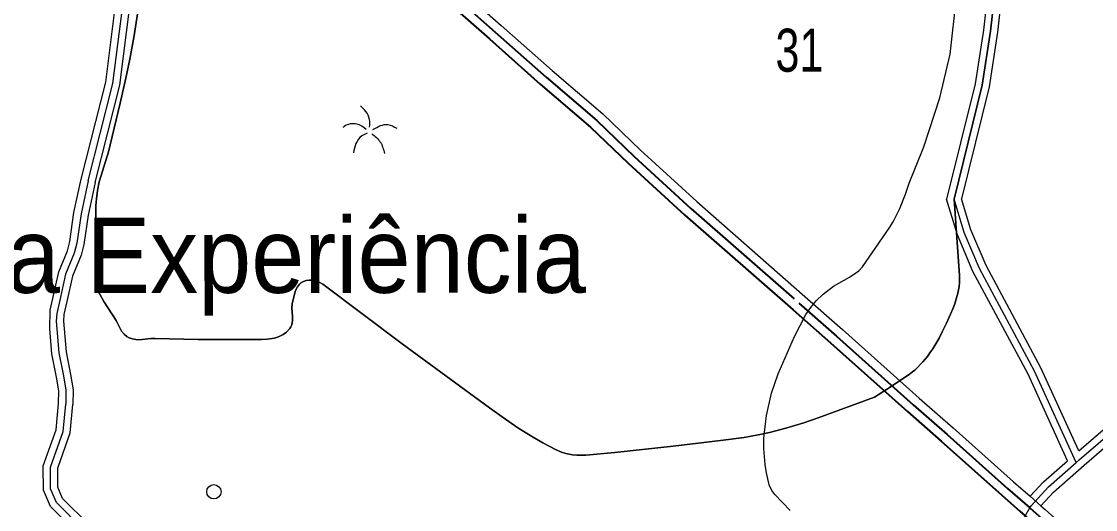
# Model space of a CAD drawing. Extents: x -64005 to -55000, y -89025 to -80000.
# Drawn here: x -59654 to -58155, y -88019 to -87338 of the extents above; entities that cross this region are included whole.
import ezdxf
from ezdxf.enums import TextEntityAlignment as Align

# ---------------------------------------------------------------- set-up
doc = ezdxf.new("R2010")
doc.units = 0
doc.header["$LTSCALE"] = 32
doc.linetypes.add('LONG_DASHED', pattern=[7.5, 6, -1.5])
for name, color, linetype, lineweight in [('1', 7, 'Continuous', 25), ('24', 7, 'Continuous', 25), ('33', 7, 'Continuous', 25), ('39', 7, 'LONG_DASHED', 25), ('5', 7, 'Continuous', 40), ('52', 7, 'Continuous', 25), ('8', 7, 'Continuous', 25)]:
    doc.layers.add(name, color=color, linetype=linetype, lineweight=lineweight)
doc.layers.add('38', color=7, linetype='Continuous')
doc.layers.add('46', color=7, linetype='Continuous')

msp = doc.modelspace()

# ---------------------------------------------------------------- linework, layer by layer
at = {"layer": '1'}
for points in [[(-58372.57, -87444.5), (-58357.94, -87383.71), (-58349.09, -87304.05)], [(-58581.45, -88020.12), (-58602.83, -87997.7), (-58606.93, -87992.15), (-58610.51, -87984.27), (-58614.6, -87967.43), (-58616.34, -87956.15), (-58618.21, -87933.44), (-58618.21, -87919.36), (-58614.29, -87887.77), (-58607.52, -87856.57), (-58598.26, -87829.54), (-58575.41, -87777.44), (-58559.27, -87746.76), (-58552.52, -87736.86), (-58544.87, -87727.68), (-58535.38, -87718.35), (-58520.91, -87707.41), (-58498.55, -87694.48), (-58485.73, -87685.7), (-58480.34, -87680.2), (-58443.02, -87626.17), (-58437.62, -87617.28), (-58428.29, -87598.67), (-58420.21, -87578.84), (-58415.46, -87563.5), (-58394.92, -87512.76), (-58372.57, -87444.5)]]:
    msp.add_lwpolyline(points, dxfattribs=at)
at = {"layer": '24'}
for points in [[(-58405.8, -86742.35), (-58406.44, -86764.44), (-58391.51, -86792.37), (-58361.63, -86839.13), (-58344.75, -86885.58), (-58353.83, -86937.54), (-58347.33, -86964.82), (-58347.33, -86990.81), (-58357.71, -87023.29), (-58346.02, -87071.35), (-58304.45, -87210.36), (-58294.05, -87281.49), (-58301.84, -87351.64), (-58313.51, -87426.99), (-58352.65, -87585.71)], [(-58352.65, -87585.71), (-58313.51, -87426.99), (-58301.84, -87351.64), (-58294.05, -87281.49), (-58304.45, -87210.36), (-58346.02, -87071.35), (-58357.71, -87023.29), (-58347.33, -86990.81), (-58347.33, -86964.82), (-58353.83, -86937.54), (-58344.75, -86885.58), (-58361.63, -86839.13), (-58391.51, -86792.37), (-58406.44, -86764.44), (-58405.8, -86742.35)], [(-59539.18, -87728.63), (-59544.45, -87719.22), (-59546.89, -87714.24), (-59549.06, -87708.19), (-59550.05, -87703.26), (-59550.66, -87695.76), (-59550.53, -87608.94), (-59550.14, -87594.84), (-59549.51, -87585.45), (-59548.13, -87573.72), (-59545.64, -87561.88), (-59543.42, -87554.14), (-59534.77, -87527.32), (-59533.21, -87521.5), (-59516.24, -87451.98), (-59508.34, -87417.04), (-59502.91, -87390.62), (-59496.87, -87357.48), (-59492.18, -87327.5)], [(-59492.18, -87327.5), (-59496.87, -87357.48), (-59502.91, -87390.62), (-59508.34, -87417.04), (-59516.24, -87451.98), (-59533.21, -87521.5), (-59534.77, -87527.32), (-59543.42, -87554.14), (-59545.64, -87561.88), (-59548.13, -87573.72), (-59549.51, -87585.45), (-59550.14, -87594.84), (-59550.53, -87608.94), (-59550.66, -87695.76), (-59550.05, -87703.26), (-59549.06, -87708.19), (-59546.89, -87714.24), (-59544.45, -87719.22), (-59539.18, -87728.63)], [(-58352.65, -87585.71), (-58348.83, -87639.11), (-58345.02, -87692.52), (-58344.86, -87695.94), (-58344.86, -87699.13), (-58344.99, -87702.11), (-58345.55, -87707.68), (-58346.33, -87712.53), (-58347.24, -87716.75), (-58348.17, -87720.44), (-58350.1, -87726.86), (-58351.76, -87731.67), (-58354.53, -87738.86), (-58357.55, -87746.04), (-58363.31, -87758.93), (-58368.63, -87770.02), (-58373.58, -87779.5), (-58378.16, -87787.56), (-58382.41, -87794.39), (-58386.32, -87800.18), (-58389.9, -87805.08), (-58393.17, -87809.23), (-58396.14, -87812.74), (-58398.83, -87815.73), (-58403.73, -87820.73), (-58407.6, -87824.29), (-58410.6, -87826.84), (-58415.28, -87830.47), (-58420.19, -87833.85), (-58441.99, -87847.96), (-58463.79, -87862.07)], [(-58463.79, -87862.07), (-58441.99, -87847.96), (-58420.19, -87833.85), (-58415.28, -87830.47), (-58410.6, -87826.84), (-58407.6, -87824.29), (-58403.73, -87820.73), (-58398.83, -87815.73), (-58396.14, -87812.74), (-58393.17, -87809.23), (-58389.9, -87805.08), (-58386.32, -87800.18), (-58382.41, -87794.39), (-58378.16, -87787.56), (-58373.58, -87779.5), (-58368.63, -87770.02), (-58363.31, -87758.93), (-58357.55, -87746.04), (-58354.53, -87738.86), (-58351.76, -87731.67), (-58350.1, -87726.86), (-58348.17, -87720.44), (-58347.24, -87716.75), (-58346.33, -87712.53), (-58345.55, -87707.68), (-58344.99, -87702.11), (-58344.86, -87699.13), (-58344.86, -87695.94), (-58345.02, -87692.52), (-58348.83, -87639.11), (-58352.65, -87585.71)], [(-58463.79, -87862.07), (-58542.14, -87890.69), (-58562.08, -87897.62), (-58587.33, -87905.35), (-58610.35, -87911.27), (-58625.84, -87914.62), (-58645.34, -87918.05), (-58678.46, -87922.66), (-58744.83, -87930.51), (-58826.07, -87939.25), (-58866.7, -87942.95), (-58879, -87943.1), (-58885.13, -87942.47), (-58894.26, -87940.58), (-58900.29, -87938.67), (-58907.73, -87935.5), (-58926.58, -87925.72), (-58940.9, -87917.54), (-58961.44, -87904.7), (-58983.49, -87889.66), (-59000.99, -87877.07), (-59122.86, -87787.54), (-59233.53, -87704.25), (-59238.53, -87701.39), (-59243.15, -87699.78), (-59248.69, -87698.83), (-59252.43, -87698.76), (-59256.97, -87699.38), (-59260.39, -87700.48), (-59264.22, -87702.69), (-59266.21, -87704.48), (-59268.85, -87707.97), (-59271.45, -87713.07), (-59273.22, -87718.33), (-59276.35, -87731.95), (-59276.59, -87737.71), (-59275.71, -87749.47), (-59275.76, -87755.29), (-59276.91, -87760.95), (-59278.08, -87763.7), (-59279.74, -87766.37), (-59284.43, -87771.39), (-59288.77, -87774.65), (-59292.42, -87776.69), (-59295.26, -87777.92), (-59301.11, -87779.71), (-59311.2, -87781.13), (-59319.33, -87781.37), (-59407.62, -87781.38)], [(-59407.62, -87781.38), (-59319.33, -87781.37), (-59311.2, -87781.13), (-59301.11, -87779.71), (-59295.26, -87777.92), (-59292.42, -87776.69), (-59288.77, -87774.65), (-59284.43, -87771.39), (-59279.74, -87766.37), (-59278.08, -87763.7), (-59276.91, -87760.95), (-59275.76, -87755.29), (-59275.71, -87749.47), (-59276.59, -87737.71), (-59276.35, -87731.95), (-59273.22, -87718.33), (-59271.45, -87713.07), (-59268.85, -87707.97), (-59266.21, -87704.48), (-59264.22, -87702.69), (-59260.39, -87700.48), (-59256.97, -87699.38), (-59252.43, -87698.76), (-59248.69, -87698.83), (-59243.15, -87699.78), (-59238.53, -87701.39), (-59233.53, -87704.25), (-59122.86, -87787.54), (-59000.99, -87877.07), (-58983.49, -87889.66), (-58961.44, -87904.7), (-58940.9, -87917.54), (-58926.58, -87925.72), (-58907.73, -87935.5), (-58900.29, -87938.67), (-58894.26, -87940.58), (-58885.13, -87942.47), (-58879, -87943.1), (-58866.7, -87942.95), (-58826.07, -87939.25), (-58744.83, -87930.51), (-58678.46, -87922.66), (-58645.34, -87918.05), (-58625.84, -87914.62), (-58610.35, -87911.27), (-58587.33, -87905.35), (-58562.08, -87897.62), (-58542.14, -87890.69), (-58463.79, -87862.07)], [(-59407.62, -87781.38), (-59467.31, -87780.14), (-59473.45, -87780.37), (-59485.84, -87781.64), (-59492, -87781.82), (-59499.07, -87780.87), (-59504, -87779.07), (-59506.91, -87777.42), (-59510.73, -87774.37), (-59514.38, -87769.9), (-59522.02, -87755.27), (-59539.18, -87728.63)], [(-59539.18, -87728.63), (-59522.02, -87755.27), (-59514.38, -87769.9), (-59510.73, -87774.37), (-59506.91, -87777.42), (-59504, -87779.07), (-59499.07, -87780.87), (-59492, -87781.82), (-59485.84, -87781.64), (-59473.45, -87780.37), (-59467.31, -87780.14), (-59407.62, -87781.38)]]:
    msp.add_lwpolyline(points, dxfattribs=at)
at = {"layer": '33'}
for points in [[(-59168.31, -87485.48), (-59168.31, -87474.64), (-59173.65, -87463.5), (-59180.89, -87455.8)], [(-59172.84, -87488.57), (-59186.04, -87481.15), (-59203.82, -87484.55), (-59205.52, -87485.87)], [(-59163.57, -87488.54), (-59142.59, -87481.72), (-59130.49, -87486.98)], [(-59171.56, -87494), (-59179.28, -87497.72), (-59187.3, -87508.28), (-59190.94, -87521.4)], [(-59165.36, -87494.54), (-59153.42, -87506.16), (-59147.44, -87522.08)]]:
    msp.add_spline(points, degree=3, dxfattribs=at)
at = {"layer": '39'}
msp.add_line((-58246.87, -88016.59), (-58245.2, -88013.75), dxfattribs=at)
for points in [[(-58388.82, -86796.58), (-58361.63, -86839.13), (-58344.75, -86885.58), (-58353.83, -86937.54), (-58347.33, -86964.82), (-58347.33, -86990.81), (-58357.71, -87023.29), (-58346.02, -87071.35), (-58304.45, -87210.36), (-58300.55, -87238.61), (-58294.05, -87281.49), (-58301.84, -87351.64), (-58313.51, -87426.99), (-58352.65, -87585.7)], [(-59561.19, -87560.44), (-59526.62, -87424.65), (-59512.83, -87315.77)], [(-59561.19, -87560.44), (-59570.95, -87606.3), (-59576.67, -87647), (-59580.39, -87660.95), (-59592.54, -87690.27), (-59600.73, -87726.54), (-59604.7, -87745.38), (-59605.69, -87756.07), (-59601.72, -87800.26), (-59595.27, -87832.12), (-59592.04, -87852.35), (-59592.33, -87871.59)], [(-58182.21, -87953.29), (-58240.31, -87825.64), (-58317.07, -87682.5), (-58338.57, -87632.18), (-58352.65, -87585.7)], [(-58182.21, -87953.29), (-58177.85, -87949.47), (-58121.66, -87900.97), (-58087.04, -87880.18), (-58024.11, -87854.8), (-57970.24, -87836.31), (-57937.13, -87827.07), (-57900.19, -87817.05), (-57830.16, -87787.78), (-57722.76, -87740.9), (-57678.89, -87725.49), (-57663.5, -87723.18), (-57628.09, -87720.87), (-57598.07, -87715.47), (-57547.28, -87697.75), (-57499.56, -87673.88), (-57497.85, -87673.45)], [(-59256.17, -88638.55), (-59295.32, -88561.98), (-59358.09, -88431.71), (-59410.32, -88319.47), (-59427.49, -88288.86), (-59446.73, -88259.27), (-59494.1, -88203.58), (-59520.16, -88153.82), (-59545.03, -88075.62), (-59567.77, -88046.45), (-59605.25, -88008.97), (-59613.46, -87989.81), (-59613.71, -87959.51), (-59595.95, -87909.73), (-59592.33, -87871.59)], [(-58245.2, -88013.75), (-58220.95, -87987.18), (-58182.21, -87953.29)], [(-58342.56, -88282.98), (-58317.71, -88217.55), (-58275.99, -88066.09), (-58246.87, -88016.59)]]:
    msp.add_lwpolyline(points, dxfattribs=at)
at = {"layer": '39', "lineweight": 35}
for points in [[(-59435.7, -86959.89), (-59375.54, -87013.62), (-59274.66, -87101.14), (-59215.24, -87155.16), (-59168.07, -87198.55), (-59078.62, -87277.01), (-58992.83, -87353), (-58921.84, -87415.83), (-58851.39, -87476.01), (-58798.93, -87526.44), (-58720.11, -87598.64), (-58569.07, -87730.8), (-58516.61, -87777.1), (-58409.54, -87872.88), (-58362.37, -87914.22), (-58277.86, -87989.27), (-58246.87, -88016.59)], [(-58246.87, -88016.59), (-58233.78, -88028.13), (-58193.22, -88064.51), (-58136.94, -88117.65), (-58080.08, -88155.27), (-58017.22, -88193.57), (-57965.64, -88220.02), (-57878.79, -88263), (-57771.46, -88314.19), (-57685.05, -88348.91), (-57522.45, -88430.26), (-57438.68, -88470.35), (-57223.79, -88577.19), (-57140.91, -88616.87), (-57004.64, -88685.19)]]:
    msp.add_lwpolyline(points, dxfattribs=at)
at = {"layer": '5', "lineweight": 25}
msp.add_line((-58246.45, -88000.3), (-58231.45, -88013.52), dxfattribs=at)
for points in [[(-59422.79, -86954.66), (-59367.27, -87004.24), (-59266.36, -87091.79), (-59206.8, -87145.93), (-59159.72, -87189.25), (-59070.35, -87267.62), (-58984.54, -87343.64), (-58913.64, -87406.39), (-58842.99, -87466.74), (-58790.38, -87517.32), (-58711.77, -87589.33), (-58560.82, -87721.41), (-58508.3, -87767.76), (-58401.25, -87863.52), (-58354.1, -87904.85), (-58269.58, -87979.91), (-58246.45, -88000.3)], [(-58231.45, -88013.52), (-58225.47, -88018.79), (-58184.75, -88055.3), (-58129.14, -88107.82), (-58073.37, -88144.72), (-58011.11, -88182.66), (-57960.01, -88208.86), (-57873.33, -88251.76), (-57766.43, -88302.74), (-57679.91, -88337.5), (-57516.95, -88419.03), (-57433.2, -88459.12), (-57218.31, -88565.96), (-57135.41, -88605.65), (-57006.45, -88670.3)]]:
    msp.add_lwpolyline(points, dxfattribs=at)
at = {"layer": '5'}
msp.add_lwpolyline([(-59432.95, -86979.11), (-59383.8, -87023), (-59282.96, -87110.49), (-59223.68, -87164.38), (-59176.42, -87207.85), (-59086.89, -87286.39), (-59001.12, -87362.36), (-58930.04, -87425.26), (-58859.79, -87485.28), (-58807.48, -87535.56), (-58728.45, -87607.95), (-58577.32, -87740.19), (-58524.91, -87786.44), (-58417.83, -87882.24), (-58370.64, -87923.59), (-58286.15, -87998.63), (-58260.96, -88020.83), (-58245.68, -88034.3)], dxfattribs=at)
at = {"layer": '52'}
msp.add_circle((-59385.63, -87993.98), 10, dxfattribs=at)
at = {"layer": '8', "linetype": 'LONG_DASHED'}
for points in [[(-58304.13, -87281.69), (-58311.76, -87350.32), (-58323.32, -87425.02), (-58363.02, -87585.98)], [(-59570.92, -87558.15), (-59536.41, -87422.59), (-59522.78, -87314.77)], [(-59602.32, -87871.05), (-59602.05, -87853.07), (-59605.11, -87833.9), (-59611.63, -87801.7), (-59614.49, -87766.54), (-59613.89, -87740.51), (-59610.5, -87724.41), (-59602.11, -87687.23), (-59589.88, -87657.74), (-59586.49, -87645.01), (-59580.81, -87604.56), (-59570.92, -87558.15)], [(-58194.39, -87950.66), (-58249.28, -87830.08), (-58326.25, -87686.52), (-58347.98, -87635.6), (-58363.02, -87585.98)], [(-58178.66, -87936.96), (-58127.54, -87892.84), (-58091.51, -87871.2), (-58027.6, -87845.43), (-57973.21, -87826.76), (-57939.78, -87817.43), (-57903.44, -87807.57), (-57834.79, -87778.88), (-57725.86, -87731.39), (-57681.31, -87715.74), (-57664.57, -87713.23), (-57629.3, -87710.93), (-57600.62, -87705.77), (-57551.18, -87688.52), (-57501.13, -87664)], [(-59623.67, -87957.65), (-59605.79, -87907.54), (-59602.32, -87871.05)], [(-58246.45, -88000.3), (-58227.96, -87980.03), (-58194.39, -87950.66)], [(-59271.29, -88630.96), (-59304.28, -88566.43), (-59367.17, -88435.91), (-59419.04, -88324.36), (-59436.22, -88293.75), (-59454.63, -88265.42), (-59502.44, -88209.21), (-59529.42, -88157.68), (-59554.13, -88079.99), (-59575.28, -88053.08), (-59613.68, -88014.68), (-59623.44, -87991.9), (-59624.03, -87958.67), (-59623.67, -87957.65)]]:
    msp.add_lwpolyline(points, dxfattribs=at)
at = {"layer": '8'}
for points in [[(-58283.97, -87281.29), (-58291.92, -87352.96), (-58303.7, -87428.96), (-58342.28, -87585.44)], [(-59551.43, -87562.6), (-59516.83, -87426.71), (-59502.88, -87316.77)], [(-59551.43, -87562.6), (-59561.1, -87608.04), (-59566.84, -87648.99), (-59570.9, -87664.17), (-59582.97, -87693.31), (-59590.96, -87728.67), (-59594.8, -87746.88), (-59595.65, -87756.08), (-59591.81, -87798.81), (-59585.43, -87830.34), (-59582.03, -87851.63), (-59582.34, -87872.13)], [(-58178.66, -87936.96), (-58231.34, -87821.2), (-58308.05, -87678.16), (-58329.16, -87628.76), (-58342.28, -87585.44)], [(-58231.45, -88013.52), (-58213.94, -87994.34), (-58171.29, -87957.02), (-58115.78, -87909.1), (-58082.57, -87889.16), (-58020.62, -87864.17), (-57967.27, -87845.86), (-57934.48, -87836.71), (-57896.94, -87826.53), (-57825.53, -87796.68), (-57719.66, -87750.41), (-57676.47, -87735.24), (-57662.43, -87733.13), (-57626.88, -87730.81), (-57595.52, -87725.17), (-57543.38, -87706.98), (-57500.69, -87685.48), (-57494.57, -87682.9)], [(-59603.09, -87959.51), (-59586.11, -87911.92), (-59582.34, -87872.13)], [(-59212.14, -88702.71), (-59286.36, -88557.52), (-59349.01, -88427.5), (-59401.6, -88314.56), (-59418.77, -88283.96), (-59438.82, -88253.11), (-59485.76, -88197.95), (-59510.9, -88149.96), (-59535.93, -88071.25), (-59560.26, -88039.82), (-59596.82, -88003.26), (-59603.48, -87987.72), (-59603.39, -87960.35), (-59603.09, -87959.51)]]:
    msp.add_lwpolyline(points, dxfattribs=at)

# ---------------------------------------------------------------- texts
at = {"layer": '38', "width": 0.75}
msp.add_text('31', height=60, rotation=0.007, dxfattribs=at).set_placement((-58568.44, -87408.08), align=Align.CENTER)
at = {"layer": '46', "width": 0.95}
msp.add_text('Pinhal da Experiência', height=105, rotation=0.007, dxfattribs=at).set_placement((-59511.47, -87716.54), align=Align.CENTER)

doc.saveas('drawing.dxf')
